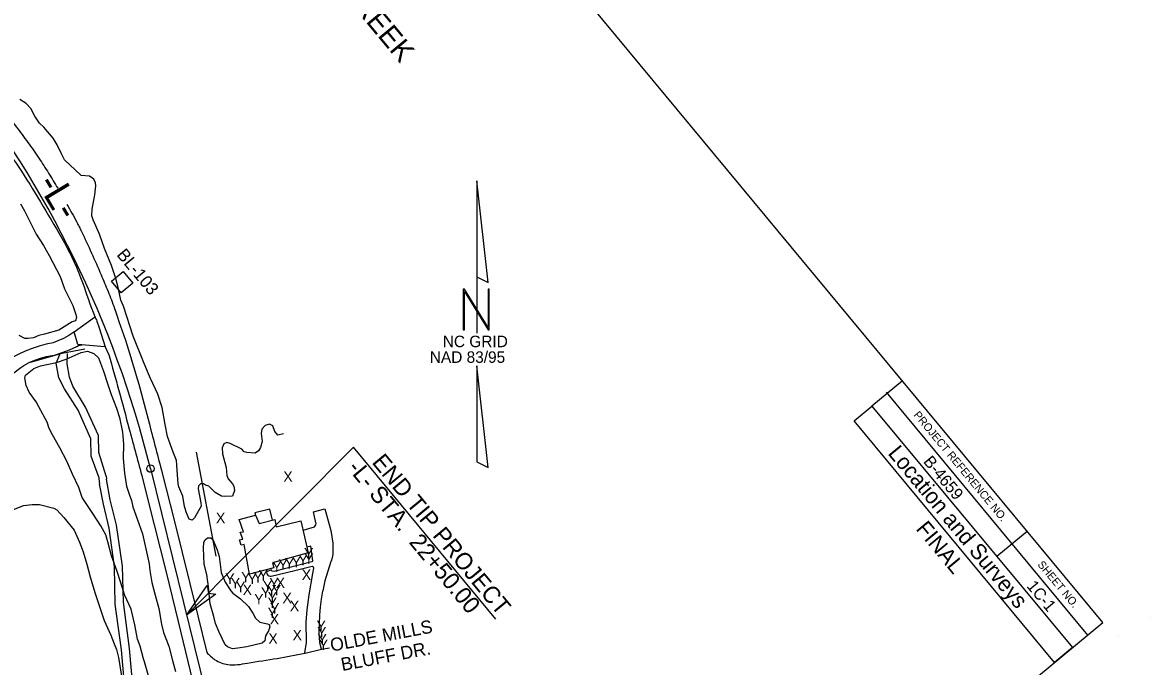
# Model space of a CAD drawing. Extents: x 2057130 to 2060012, y 687175 to 689912.
# Drawn here: x 2058941 to 2060012, y 688138 to 688750 of the extents above; entities that cross this region are included whole.
import ezdxf

# ---------------------------------------------------------------- set-up
doc = ezdxf.new("R2010")
doc.units = 0
for name, color, linetype in [('CTL North Arrow NAD 83 95 CELL', 7, 'Continuous'), ('CTL Sheet Border CELL', 7, 'Continuous'), ('CTL Supplemental Horizontal and Vertical CELL', 7, 'Continuous'), ('CTL Supplemental Horizontal and Vertical Text', 7, 'Continuous'), ('Default', 7, 'Continuous'), ('Exist Other Culture Fence Line', 7, 'Continuous'), ('Exist Roads EOP', 7, 'Continuous'), ('Exist Roads EOP Other', 7, 'Continuous'), ('Exist Roads Soil', 7, 'Continuous'), ('Old_Level_11', 7, 'Continuous'), ('Old_Level_3', 7, 'Continuous'), ('Old_Level_8', 7, 'Continuous'), ('Prop Dimension Text', 7, 'Continuous'), ('Prop Horizontal Alignment', 7, 'Continuous'), ('Prop Horizontal Alignment Station Label', 7, 'Continuous'), ('Prop Terminator CELL', 7, 'Continuous'), ('Sheet Data Field CELL', 7, 'Continuous')]:
    doc.layers.add(name, color=color, linetype=linetype)

msp = doc.modelspace()

# ---------------------------------------------------------------- linework, layer by layer
at = {"layer": 'CTL North Arrow NAD 83 95 CELL'}
for points in [[(2059372.5, 688599.6), (2059372.5, 688508.4), (2059383.2, 688503.1)], [(2059359.6, 688458.1), (2059360.7, 688458.1), (2059360.7, 688494.5), (2059383.2, 688458.1), (2059384.3, 688458.1), (2059384.3, 688496.6), (2059383.2, 688496.6), (2059383.2, 688460.2), (2059360.7, 688496.6), (2059359.6, 688496.6)], [(2059372.5, 688332.6), (2059383.2, 688327.3), (2059372.5, 688423.8)]]:
    msp.add_lwpolyline(points, close=True, dxfattribs=at)
msp.add_lwpolyline([(2059372.5, 688508.4), (2059372.5, 688454.8)], dxfattribs=at)
at = {"layer": 'CTL Sheet Border CELL'}
for p, q in [((2059776.8, 688409.6), (2059747.9, 688385.6)), ((2059761.3, 688398.9), (2059952.8, 688167.9)), ((2059895.5, 688266.5), (2059866.6, 688242.6)), ((2060012.5, 688184.2), (2060012.5, 688184.2)), ((2059982.3, 688167.9), (2059982.3, 688167.9))]:
    msp.add_line(p, q, dxfattribs=at)
for points in [[(2059967.3, 688179.9), (2058531.1, 689911.9), (2057318.7, 688906.6), (2058754.9, 687174.6)], [(2059747.9, 688385.6), (2059938.4, 688156), (2059921.4, 688141.9), (2059730.9, 688371.6)]]:
    msp.add_lwpolyline(points, close=True, dxfattribs=at)
at = {"layer": 'CTL Supplemental Horizontal and Vertical CELL'}
msp.add_line((2059035.7, 688503.5), (2059035.7, 688503.5), dxfattribs=at)
msp.add_lwpolyline([(2059036.7, 688513.6), (2059045.9, 688502.5), (2059034.7, 688493.3), (2059025.5, 688504.4)], close=True, dxfattribs=at)
at = {"layer": 'Exist Other Culture Fence Line'}
msp.add_line((2059124.8, 688242.9), (2059106.2, 688341.7), dxfattribs=at)
at = {"layer": 'Exist Roads EOP'}
for p, q in [((2059011.6, 688466.4), (2059013.7, 688460.1)), ((2059031, 688471), (2059032.5, 688466)), ((2059038.9, 688448.2), (2059041.3, 688440.1)), ((2059038.9, 688448.2), (2059041.3, 688440.1)), ((2059019.5, 688441.9), (2059022.9, 688434.4))]:
    msp.add_line(p, q, dxfattribs=at)
for points in [[(2059013.7, 688460.1), (2059019.5, 688441.9)], [(2059032.5, 688466), (2059038.9, 688448.2)], [(2059055, 688316.7), (2059066, 688272.7), (2059077.4, 688227.6), (2059088.7, 688180.9), (2059100.3, 688133.6), (2059110.5, 688090.8), (2059121.2, 688047.3), (2059135.1, 687991.8)], [(2059073.6, 688321.9), (2059085, 688277.1), (2059107.6, 688186.2), (2059115.9, 688151.5)], [(2059073.6, 688321.9), (2059085, 688277.1), (2059107.6, 688186.2), (2059115.9, 688151.5)], [(2059182.9, 688145.8), (2059202.6, 688149.3), (2059209.4, 688150.6), (2059225, 688154.4), (2059232.5, 688155.9)], [(2059182.9, 688145.8), (2059202.6, 688149.3), (2059209.4, 688150.6), (2059225, 688154.4), (2059232.5, 688155.9)]]:
    msp.add_lwpolyline(points, dxfattribs=at)
for points in [[(2058873, 688726), (2058891.3, 688704.8), (2058913.3, 688678.9), (2058935, 688651.1), (2058946, 688636.3), (2058951.3, 688628.8), (2058956.5, 688621.2), (2058965.7, 688607), (2058974.4, 688592.6)], [(2058856.6, 688711.7), (2058876, 688692.6), (2058897.4, 688666.2), (2058918.6, 688638.9), (2058939.9, 688608.9), (2058960.5, 688575.4), (2058980.7, 688540.9), (2058998, 688503.1), (2059009.6, 688470.8), (2059011.6, 688466.4)], [(2058983.2, 688577.3), (2058987.8, 688569.1), (2058992.5, 688560.4), (2058994.7, 688556), (2058996.9, 688551.6), (2059006.5, 688531.1), (2059015.6, 688510.4), (2059018.9, 688502.5), (2059022.2, 688494.6), (2059028.3, 688478.5), (2059031, 688471)], [(2059022.9, 688434.4), (2059032.5, 688400.4), (2059042.3, 688363.7), (2059055, 688316.7)], [(2059041.3, 688440.1), (2059051.4, 688406.3), (2059061.5, 688368.4), (2059073.6, 688321.9)], [(2059041.3, 688440.1), (2059051.4, 688406.3), (2059061.5, 688368.4), (2059073.6, 688321.9)], [(2059115.9, 688151.5), (2059123.8, 688144.5), (2059136, 688139.9), (2059154.6, 688141.2), (2059182.9, 688145.8)], [(2059115.9, 688151.5), (2059123.8, 688144.5), (2059136, 688139.9), (2059154.6, 688141.2), (2059182.9, 688145.8)]]:
    msp.add_spline(points, degree=3, dxfattribs=at)
at = {"layer": 'Exist Roads EOP Other'}
for points in [[(2059019.2, 688441.8), (2058993.6, 688444.2), (2058989.9, 688456.1), (2059009.3, 688470.1)], [(2058990, 688456), (2058989.7, 688455.8), (2058984.9, 688452.7), (2058979.8, 688449.9), (2058974.6, 688447.5), (2058970.2, 688445.7), (2058963.4, 688444.3), (2058956.7, 688442.5), (2058950.1, 688440.4), (2058943.6, 688437.8), (2058937.3, 688434.9), (2058931.2, 688431.7), (2058925.3, 688428.1), (2058919.6, 688424.1), (2058919.1, 688423.8), (2058914.7, 688420.3), (2058910.5, 688416.5), (2058906.6, 688412.3), (2058903, 688408), (2058899.7, 688403.4), (2058896.7, 688398.5), (2058894.5, 688394.5), (2058887.3, 688384.8)], [(2058902.6, 688370.2), (2058901.6, 688374.7), (2058901, 688382.8), (2058902.2, 688387.2), (2058909.4, 688395.9), (2058916.5, 688402.9), (2058923.9, 688409.7), (2058931.5, 688416.1), (2058939.4, 688422.2), (2058942.2, 688424.2), (2058947.3, 688426.9), (2058952.6, 688429.2), (2058958, 688431.1), (2058963.6, 688432.6), (2058969.2, 688433.8), (2058971.3, 688434.1), (2058978.5, 688436.5), (2058985.5, 688439.2), (2058992.4, 688442.3), (2058994.1, 688443.1), (2058997.5, 688443.9)]]:
    msp.add_lwpolyline(points, dxfattribs=at)
at = {"layer": 'Exist Roads Soil'}
for p, q in [((2059013.1, 688319), (2059014.2, 688311.6)), ((2059020.5, 688318.9), (2059020.7, 688316))]:
    msp.add_line(p, q, dxfattribs=at)
for points in [[(2059000.2, 688439.8), (2058978.3, 688435.5), (2058948.1, 688426.9)], [(2059013.1, 688319), (2059006.2, 688338), (2059005.8, 688354.5), (2058993.9, 688381.6), (2058980.8, 688402), (2058975.3, 688412.6), (2058972.8, 688426.4), (2058976.5, 688434.7)], [(2059020.5, 688318.9), (2059013.6, 688341.6), (2059013.1, 688357.6), (2059000.9, 688384.5), (2058988.9, 688404.6), (2058985.6, 688413.1), (2058983.3, 688425.9), (2058983.6, 688435.6)], [(2059052.2, 687995.2), (2059048.6, 688004.7), (2059036.6, 688012), (2059024.3, 688021.4), (2059024.5, 688046.5), (2059027.8, 688073.7), (2059027.7, 688086.5), (2059036.8, 688100.1), (2059038.4, 688113.9), (2059035.1, 688154), (2059029.1, 688197.2), (2059028.3, 688232.7), (2059023.4, 688269.4), (2059017.9, 688292.4), (2059014.2, 688311.6)], [(2059064.5, 687999), (2059049.5, 688014.7), (2059038.8, 688019.5), (2059031.5, 688025.9), (2059031.5, 688043.3), (2059034.2, 688073.9), (2059035.5, 688086), (2059043.3, 688097.2), (2059046.4, 688112.6), (2059042.5, 688155.2), (2059036.9, 688199.3), (2059035.9, 688233.3), (2059030.1, 688272.5), (2059024.3, 688296.5), (2059020.7, 688316)]]:
    msp.add_lwpolyline(points, dxfattribs=at)
at = {"layer": 'Old_Level_11'}
for points in [[(2059087.7, 688329.4), (2059087.3, 688334), (2059084.2, 688341.7), (2059078.8, 688356.6), (2059076.6, 688368), (2059073.7, 688384.4), (2059069.4, 688397), (2059062.5, 688411.9), (2059059.8, 688418.6), (2059056, 688427.7), (2059046, 688452.1), (2059037, 688480.5), (2059034.5, 688486.2), (2059031.9, 688498.2), (2059029.7, 688507), (2059025.4, 688519.2), (2059018.9, 688535.3), (2059014, 688548.9), (2059008, 688562.8), (2059006.8, 688566.5), (2059007.2, 688572.7), (2059009.7, 688586.3), (2059010.6, 688594.9), (2059010.4, 688597.8), (2059008.8, 688601.4), (2059004.5, 688604), (2058996.8, 688604.8), (2058990.9, 688610.1), (2058980.8, 688619.8), (2058978.1, 688625.3), (2058973.8, 688634), (2058970, 688640.3), (2058961.2, 688650.6), (2058957.1, 688654.6), (2058952.8, 688661.3), (2058949, 688668.5), (2058944.5, 688673.1), (2058938.3, 688676.9)], [(2058938.9, 688577.8), (2058942.9, 688571.3), (2058949.6, 688557.8), (2058953.9, 688549), (2058960.9, 688538.4), (2058966.2, 688528.8), (2058976.6, 688508.7), (2058980.7, 688497.2), (2058988.6, 688481.2), (2058991.6, 688472.7), (2058992.2, 688469.7), (2058991.2, 688466.7), (2058988.2, 688465.7), (2058975.3, 688457.9), (2058961.9, 688454), (2058956.4, 688452.7), (2058951.5, 688450.5), (2058946, 688449.7), (2058943.3, 688449.9), (2058937.9, 688452.6)], [(2059061.4, 688126.9), (2059056.8, 688142.6), (2059055.9, 688145.3), (2059052.7, 688157.3), (2059050.3, 688163.9), (2059047.8, 688177.6), (2059044.1, 688192.6), (2059038.1, 688205.5), (2059034.1, 688218.4), (2059030.8, 688228.5), (2059025.6, 688243.2), (2059022.1, 688256.7), (2059020, 688263.3), (2059015.5, 688271.8), (2059007.7, 688283.5), (2058997.5, 688298.6), (2058994.6, 688308.3), (2058988.4, 688320.8), (2058982.9, 688333.2), (2058976.3, 688346), (2058969.4, 688358.3), (2058966.2, 688364.2), (2058964.5, 688370.3), (2058956.6, 688384.9), (2058954, 688389.7), (2058947.2, 688398.8), (2058944.3, 688405.3), (2058943.1, 688412.5), (2058943.7, 688414.9), (2058951.7, 688421.3), (2058958.1, 688423.9), (2058973.3, 688427), (2058982.3, 688430.1), (2058996.8, 688436.6), (2059002.6, 688437.9), (2059008.7, 688435.6), (2059013.1, 688431.5), (2059017.8, 688418.7), (2059021.8, 688407.1), (2059025.1, 688396.6), (2059030.2, 688383.5), (2059033.1, 688374.6), (2059035.8, 688360.9), (2059037, 688349.5), (2059036.7, 688335.9), (2059037.7, 688321.9), (2059039.8, 688309.5), (2059042.3, 688301.9), (2059044.6, 688295.7), (2059045.7, 688289.8), (2059050.1, 688277.4), (2059054.9, 688264.1), (2059058.1, 688249.8), (2059061.4, 688235.7), (2059062, 688229.4), (2059063.9, 688217.8), (2059066.9, 688205.8), (2059070.4, 688193.3), (2059073.1, 688178.2), (2059075, 688170.5), (2059080, 688157.3), (2059083.5, 688143.9), (2059086.4, 688133.2)], [(2059188.8, 688359.3), (2059183.6, 688357.8), (2059180.6, 688361.3), (2059178.6, 688366.7), (2059175.5, 688368.4), (2059171.5, 688367), (2059168.4, 688363.7), (2059167.6, 688359.6), (2059168.7, 688352), (2059167, 688346.1), (2059165, 688343), (2059162, 688340.9), (2059154.1, 688341.4), (2059151.5, 688342.2), (2059149.4, 688344.6), (2059138.1, 688350.1), (2059135.1, 688351), (2059132.2, 688349.6), (2059130.7, 688346), (2059130.9, 688340.2), (2059134.5, 688327.2), (2059135, 688319.6), (2059136.4, 688316.6), (2059140.3, 688311.8), (2059141.7, 688309.4), (2059142.4, 688305.3), (2059140.5, 688300), (2059132.9, 688299.6), (2059129.9, 688300.1), (2059124.1, 688303.6), (2059118, 688309.4), (2059114.9, 688310.3), (2059112.8, 688311.8), (2059110.1, 688311.6), (2059108.1, 688309.8), (2059107.7, 688306.9), (2059110.5, 688293.6), (2059110.8, 688290.4), (2059104.3, 688279.4), (2059102, 688277.2), (2059099.4, 688278.1), (2059096.7, 688284.2), (2059094.9, 688290.3), (2059093.2, 688300.1), (2059089.3, 688308.8), (2059088.7, 688311.6), (2059088.2, 688320.3), (2059087.7, 688329.4)], [(2058927, 688285), (2058941.8, 688291.2), (2058950.2, 688292.1), (2058957.2, 688292.1), (2058970.7, 688288.5), (2058973.5, 688287), (2058980.1, 688279.6), (2058990.1, 688267.6), (2058995.1, 688256.2), (2058998.5, 688247.1), (2059001.9, 688235.4), (2059005.1, 688223.2), (2059009.5, 688208.4), (2059013, 688197.9), (2059018.5, 688181.9), (2059024.9, 688167.8), (2059027.9, 688159.5), (2059030.1, 688154.2), (2059032.2, 688146.5), (2059035.1, 688129)], [(2059168.7, 688160.1), (2059154.2, 688156.8), (2059145.6, 688155.4), (2059140.4, 688155), (2059135.6, 688156.7), (2059133.6, 688158.6), (2059127.9, 688170.6), (2059124.4, 688178.8), (2059122.6, 688185.5), (2059119.3, 688197.7), (2059117.5, 688213.7), (2059115.9, 688225.6), (2059113.5, 688235.2), (2059112.8, 688250.6), (2059113.3, 688256.2), (2059114.5, 688258.6), (2059116.8, 688260.3), (2059119.9, 688260.3), (2059121.8, 688258.7), (2059126, 688249), (2059127.8, 688242.5), (2059129.7, 688227.4), (2059133.5, 688218.1), (2059138.7, 688209.9), (2059140.8, 688207.8), (2059148.1, 688202.5), (2059155.6, 688195), (2059159.8, 688188.8), (2059162.4, 688183.9), (2059166.5, 688180.3), (2059173.6, 688178.7), (2059175.3, 688177.9), (2059175.9, 688175.6), (2059174.7, 688171.9), (2059171.8, 688167.3), (2059171.3, 688162.5), (2059168.7, 688160.1)]]:
    msp.add_lwpolyline(points, dxfattribs=at)
at = {"layer": 'Old_Level_3'}
for points in [[(2059207.5, 688267.6), (2059218.3, 688270.9), (2059219.1, 688271.8), (2059219.6, 688272.8), (2059219.8, 688274), (2059219.7, 688274.7), (2059217.3, 688285), (2059228.2, 688287.8), (2059233.8, 688267.4), (2059234.9, 688261.3), (2059235.6, 688255.2), (2059235.9, 688249), (2059235.9, 688248.2), (2059235.7, 688244.8), (2059235.1, 688241.5), (2059234.1, 688238.3), (2059233.9, 688238), (2059230.9, 688228.8), (2059228.3, 688219.4), (2059226.1, 688210), (2059226, 688209.6), (2059224.6, 688202.2), (2059223.6, 688194.6), (2059223, 688187.2), (2059222.3, 688170.2), (2059223.1, 688161), (2059224.7, 688154.8)], [(2059216.7, 688238.6), (2059214.7, 688252.5), (2059211.1, 688251.5)], [(2059209.1, 688151), (2059210.8, 688161), (2059210.5, 688180.1), (2059211.4, 688191.8), (2059213.2, 688206.1), (2059216.7, 688226.3), (2059217.7, 688231.6), (2059217.4, 688232.6), (2059216.8, 688233.2)], [(2059209.2, 688151), (2059209.1, 688151)]]:
    msp.add_lwpolyline(points, dxfattribs=at)
at = {"layer": 'Old_Level_8'}
for points in [[(2059178.5, 688277.2), (2059176, 688287.5), (2059161.7, 688284), (2059162.3, 688281.9)], [(2059156.7, 688225.8), (2059151.5, 688253.9), (2059148.6, 688253.3), (2059147.2, 688258.5), (2059150.1, 688259.1), (2059147.8, 688265.6), (2059150.9, 688266.2), (2059146.9, 688277.9), (2059162.2, 688282), (2059165.9, 688274.1), (2059180.5, 688277.7), (2059182, 688270.8), (2059205.5, 688276.5), (2059212.3, 688246.1), (2059178.3, 688236.5), (2059179.7, 688232), (2059156.7, 688225.8)], [(2059216.7, 688238.6), (2059216.2, 688238), (2059215.7, 688237.5), (2059179.9, 688228.5), (2059178.1, 688228.8), (2059177.6, 688229.4), (2059177.4, 688230), (2059172.6, 688228.1), (2059173.2, 688226), (2059174, 688225), (2059175.1, 688224.2), (2059176.3, 688223.8), (2059177.1, 688223.8), (2059199.6, 688229.4), (2059216.1, 688233.5), (2059216.8, 688233.2)]]:
    msp.add_lwpolyline(points, dxfattribs=at)
at = {"layer": 'Prop Horizontal Alignment'}
msp.add_line((2059062.5, 688326.2), (2059144.5, 687993.8), dxfattribs=at)
for radius in [3.55, 0.114]:
    msp.add_circle((2059062.5, 688326.2), radius, dxfattribs=at)
msp.add_arc((2058091.6, 688086.7), 1000, 13.8586, 62.5059, dxfattribs=at)
at = {"layer": 'Prop Horizontal Alignment Station Label'}
for p, q in [((2059255.3, 688346.4), (2059096.8, 688186.9)), ((2059390.7, 688183.2), (2059255.3, 688346.4))]:
    msp.add_line(p, q, dxfattribs=at)
at = {"layer": 'Prop Terminator CELL'}
msp.add_lwpolyline([(2059124.7, 688206.8), (2059096.8, 688186.9), (2059116.4, 688215.2), (2059117.6, 688207.9)], close=True, dxfattribs=at)

# ---------------------------------------------------------------- texts
at = {"layer": 'CTL North Arrow NAD 83 95 CELL'}
for s, p in [('NC GRID', (2059340.2, 688441.6)), ('NAD 83/95', (2059327.9, 688426.7))]:
    msp.add_text(s, height=10.94, dxfattribs=at).set_placement(p)
at = {"layer": 'CTL Sheet Border CELL'}
for s, height, p in [('PROJECT REFERENCE NO.', 7.5, (2059787, 688376.9)), ('Location and Surveys', 15, (2059762.4, 688340.4)), ('FINAL', 15, (2059789, 688268.6)), ('SHEET NO.', 7.5, (2059904.8, 688234.7))]:
    msp.add_text(s, height=height, rotation=309.6672, dxfattribs=at).set_placement(p)
at = {"layer": 'CTL Supplemental Horizontal and Vertical Text'}
msp.add_text('BL-103', height=11.79, rotation=309.6672, dxfattribs=at).set_placement((2059029.8, 688529.2))
at = {"layer": 'Default'}
for s, p in [('OLDE MILLS', (2059234.5, 688152.1)), ('BLUFF DR.', (2059244.7, 688133.7))]:
    msp.add_text(s, height=12.5, rotation=10.692, dxfattribs=at).set_placement(p)
at = {"layer": 'Old_Level_11'}
for s, p in [('X', (2059188.7, 688313.6)), ('X', (2059124.7, 688274.2)), ('Y', (2059190.1, 688231.1)), ('Y', (2059196.6, 688232.4)), ('Y', (2059203, 688234.3)), ('Y', (2059208.4, 688240.6)), ('Y', (2059208.5, 688235.6)), ('Y', (2059178.1, 688227.8)), ('Y', (2059184, 688230)), ('Y', (2059133.5, 688216.5)), ('Y', (2059138.7, 688212.3)), ('Y', (2059148.6, 688218)), ('Y', (2059154.7, 688216.6)), ('Y', (2059160.1, 688217.9)), ('Y', (2059165.2, 688219.7)), ('Y', (2059169.3, 688209.6)), ('Y', (2059175.5, 688212.1)), ('X', (2059181.5, 688212.6)), ('X', (2059206.2, 688220.3)), ('Y', (2059143.7, 688208.7)), ('X', (2059150.1, 688205.9)), ('Y', (2059167.4, 688203.4)), ('Y', (2059173.2, 688205.4)), ('Y', (2059173.9, 688199)), ('Y', (2059177.8, 688205.6)), ('Y', (2059161, 688197.1)), ('Y', (2059173.8, 688193.6)), ('Y', (2059176.1, 688188.3)), ('X', (2059187.9, 688198.2)), ('X', (2059194.9, 688190.5)), ('Y', (2059173.8, 688184)), ('X', (2059175.8, 688178)), ('Y', (2059220.2, 688171.7)), ('X', (2059174.5, 688159.6)), ('X', (2059197.5, 688162.9)), ('Y', (2059220.8, 688165.7)), ('Y', (2059221.2, 688159)), ('Y', (2059222.4, 688153.7))]:
    msp.add_text(s, height=10, dxfattribs=at).set_placement(p)
at = {"layer": 'Prop Dimension Text'}
msp.add_text('-L-', height=26.25, rotation=300.8634, dxfattribs=at).set_placement((2058954.1, 688597))
at = {"layer": 'Prop Horizontal Alignment Station Label'}
for s, p in [('END TIP PROJECT ', (2059272.2, 688331.9)), ('-L- STA.  22+50.00  ', (2059249, 688326.4))]:
    msp.add_text(s, height=16, rotation=309.6672, dxfattribs=at).set_placement(p)
at = {"layer": 'Sheet Data Field CELL'}
for s, height, p in [('BRIDGE NO. 373 OVER BASAL CREEK ', 19.531, (2058996.9, 689076.1)), ('B-4659', 11.25, (2059796.1, 688332.6)), ('1C-1', 11.25, (2059894.3, 688214.2))]:
    msp.add_text(s, height=height, rotation=309.6672, dxfattribs=at).set_placement(p)

doc.saveas('drawing.dxf')
